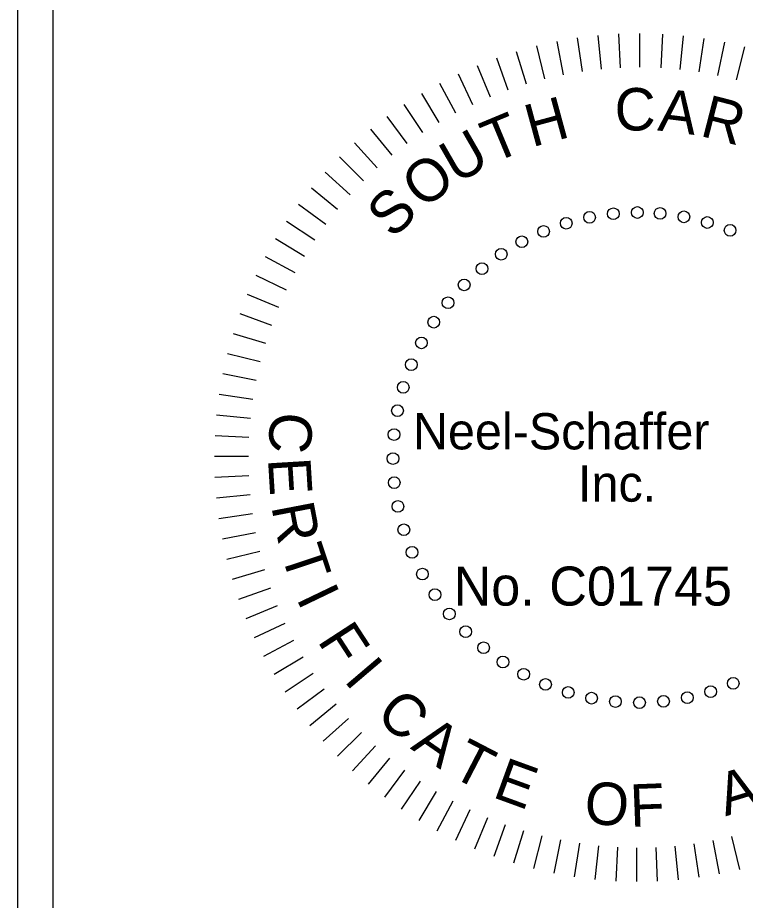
# Model space of a CAD drawing. Extents: x 1524103 to 2096450, y 1024229 to 1162569.
# Drawn here: x 2065607 to 2068303, y 1118769 to 1122041 of the extents above; entities that cross this region are included whole.
import ezdxf

# ---------------------------------------------------------------- set-up
doc = ezdxf.new("R2010")
doc.units = 0
doc.layers.add('RD_SHT_Bndy', color=7, linetype='Continuous')
doc.layers.add('RD_SHT_TX', color=7, linetype='Continuous')

msp = doc.modelspace()

# ---------------------------------------------------------------- linework, layer by layer
at = {"layer": 'RD_SHT_Bndy'}
for points in [[(2065606.8, 1117100.8), (2074607.6, 1117100.8), (2074607.6, 1124635.2), (2065606.8, 1124635.2)], [(2065737.6, 1117227.6), (2074476.9, 1117227.6), (2074476.9, 1124504.5), (2065737.6, 1124504.5)]]:
    msp.add_lwpolyline(points, close=True, dxfattribs=at)
at = {"layer": 'RD_SHT_TX'}
for p, q in [((2067680.3, 1121965.5), (2067698.7, 1121841.4)), ((2067680.3, 1121965.5), (2067698.7, 1121841.4)), ((2067680.3, 1121965.5), (2067698.7, 1121841.4)), ((2067756.9, 1121974.8), (2067769.1, 1121850)), ((2067756.9, 1121974.8), (2067769.1, 1121850)), ((2067756.9, 1121974.8), (2067769.1, 1121850)), ((2067833.7, 1121980.3), (2067839.9, 1121855)), ((2067833.7, 1121980.3), (2067839.9, 1121855)), ((2067833.7, 1121980.3), (2067839.9, 1121855)), ((2067910.8, 1121982.1), (2067910.8, 1121856.7)), ((2067910.8, 1121982.1), (2067910.8, 1121856.7)), ((2067910.8, 1121982.1), (2067910.8, 1121856.7)), ((2067996.6, 1121979.6), (2067989.8, 1121854.4)), ((2067996.6, 1121979.6), (2067989.8, 1121854.4)), ((2067996.6, 1121979.6), (2067989.8, 1121854.4)), ((2068073.5, 1121973.4), (2068060.5, 1121848.6)), ((2068073.5, 1121973.4), (2068060.5, 1121848.6)), ((2068073.5, 1121973.4), (2068060.5, 1121848.6)), ((2068149.9, 1121963.4), (2068130.8, 1121839.4)), ((2068149.9, 1121963.4), (2068130.8, 1121839.4)), ((2068149.9, 1121963.4), (2068130.8, 1121839.4)), ((2067529.1, 1121935.7), (2067559.6, 1121814)), ((2067529.1, 1121935.7), (2067559.6, 1121814)), ((2067529.1, 1121935.7), (2067559.6, 1121814)), ((2067604.4, 1121952.4), (2067628.8, 1121829.4)), ((2067604.4, 1121952.4), (2067628.8, 1121829.4)), ((2067604.4, 1121952.4), (2067628.8, 1121829.4)), ((2068225.8, 1121949.7), (2068200.6, 1121826.8)), ((2068225.8, 1121949.7), (2068200.6, 1121826.8)), ((2068225.8, 1121949.7), (2068200.6, 1121826.8)), ((2068300.8, 1121932.3), (2068269.7, 1121810.8)), ((2068300.8, 1121932.3), (2068269.7, 1121810.8)), ((2068300.8, 1121932.3), (2068269.7, 1121810.8)), ((2067454.8, 1121915.3), (2067491.2, 1121795.2)), ((2067454.8, 1121915.3), (2067491.2, 1121795.2)), ((2067454.8, 1121915.3), (2067491.2, 1121795.2)), ((2067309.6, 1121863.6), (2067357.5, 1121747.7)), ((2067309.6, 1121863.6), (2067357.5, 1121747.7)), ((2067309.6, 1121863.6), (2067357.5, 1121747.7)), ((2067381.5, 1121891.2), (2067423.8, 1121773.1)), ((2067381.5, 1121891.2), (2067423.8, 1121773.1)), ((2067381.5, 1121891.2), (2067423.8, 1121773.1)), ((2067239, 1121832.5), (2067292.6, 1121719.1)), ((2067239, 1121832.5), (2067292.6, 1121719.1)), ((2067239, 1121832.5), (2067292.6, 1121719.1)), ((2067170.1, 1121798), (2067229.2, 1121687.4)), ((2067170.1, 1121798), (2067229.2, 1121687.4)), ((2067170.1, 1121798), (2067229.2, 1121687.4)), ((2067103, 1121760.1), (2067167.4, 1121652.5)), ((2067103, 1121760.1), (2067167.4, 1121652.5)), ((2067103, 1121760.1), (2067167.4, 1121652.5)), ((2067037.7, 1121719), (2067107.4, 1121614.7)), ((2067037.7, 1121719), (2067107.4, 1121614.7)), ((2067037.7, 1121719), (2067107.4, 1121614.7)), ((2066974.6, 1121674.8), (2067049.3, 1121574)), ((2066974.6, 1121674.8), (2067049.3, 1121574)), ((2066974.6, 1121674.8), (2067049.3, 1121574)), ((2066913.8, 1121627.5), (2066993.3, 1121530.5)), ((2066913.8, 1121627.5), (2066993.3, 1121530.5)), ((2066913.8, 1121627.5), (2066993.3, 1121530.5)), ((2066855.3, 1121577.3), (2066939.4, 1121484.3)), ((2066855.3, 1121577.3), (2066939.4, 1121484.3)), ((2066855.3, 1121577.3), (2066939.4, 1121484.3)), ((2066799.3, 1121524.3), (2066887.9, 1121435.5)), ((2066799.3, 1121524.3), (2066887.9, 1121435.5)), ((2066799.3, 1121524.3), (2066887.9, 1121435.5)), ((2066746, 1121468.6), (2066838.9, 1121384.3)), ((2066746, 1121468.6), (2066838.9, 1121384.3)), ((2066746, 1121468.6), (2066838.9, 1121384.3)), ((2066695.5, 1121410.3), (2066792.4, 1121330.7)), ((2066695.5, 1121410.3), (2066792.4, 1121330.7)), ((2066695.5, 1121410.3), (2066792.4, 1121330.7)), ((2066648, 1121349.7), (2066748.6, 1121274.9)), ((2066648, 1121349.7), (2066748.6, 1121274.9)), ((2066648, 1121349.7), (2066748.6, 1121274.9)), ((2066603.4, 1121286.8), (2066707.6, 1121217)), ((2066603.4, 1121286.8), (2066707.6, 1121217)), ((2066603.4, 1121286.8), (2066707.6, 1121217)), ((2066562, 1121221.7), (2066669.5, 1121157.2)), ((2066562, 1121221.7), (2066669.5, 1121157.2)), ((2066562, 1121221.7), (2066669.5, 1121157.2)), ((2066523.9, 1121154.8), (2066634.4, 1121095.5)), ((2066523.9, 1121154.8), (2066634.4, 1121095.5)), ((2066523.9, 1121154.8), (2066634.4, 1121095.5)), ((2066489, 1121086), (2066602.3, 1121032.3)), ((2066489, 1121086), (2066602.3, 1121032.3)), ((2066489, 1121086), (2066602.3, 1121032.3)), ((2066457.6, 1121015.6), (2066573.4, 1120967.5)), ((2066457.6, 1121015.6), (2066573.4, 1120967.5)), ((2066457.6, 1121015.6), (2066573.4, 1120967.5)), ((2066429.7, 1120943.8), (2066547.7, 1120901.4)), ((2066429.7, 1120943.8), (2066547.7, 1120901.4)), ((2066429.7, 1120943.8), (2066547.7, 1120901.4)), ((2066405.3, 1120870.6), (2066525.2, 1120834.1)), ((2066405.3, 1120870.6), (2066525.2, 1120834.1)), ((2066405.3, 1120870.6), (2066525.2, 1120834.1)), ((2066384.5, 1120796.4), (2066506.1, 1120765.8)), ((2066384.5, 1120796.4), (2066506.1, 1120765.8)), ((2066384.5, 1120796.4), (2066506.1, 1120765.8)), ((2066367.4, 1120721.2), (2066490.4, 1120696.6)), ((2066367.4, 1120721.2), (2066490.4, 1120696.6)), ((2066367.4, 1120721.2), (2066490.4, 1120696.6)), ((2066354, 1120645.3), (2066478, 1120626.8)), ((2066354, 1120645.3), (2066478, 1120626.8)), ((2066354, 1120645.3), (2066478, 1120626.8)), ((2066344.3, 1120568.8), (2066469.1, 1120556.4)), ((2066344.3, 1120568.8), (2066469.1, 1120556.4)), ((2066344.3, 1120568.8), (2066469.1, 1120556.4)), ((2066338.4, 1120492), (2066463.7, 1120485.7)), ((2066338.4, 1120492), (2066463.7, 1120485.7)), ((2066338.4, 1120492), (2066463.7, 1120485.7)), ((2066336.3, 1120414.9), (2066461.7, 1120414.8)), ((2066336.3, 1120414.9), (2066461.7, 1120414.8)), ((2066336.3, 1120414.9), (2066461.7, 1120414.8)), ((2066338, 1120337.9), (2066463.2, 1120343.8)), ((2066338, 1120337.9), (2066463.2, 1120343.8)), ((2066338, 1120337.9), (2066463.2, 1120343.8)), ((2066343.4, 1120261), (2066468.2, 1120273.1)), ((2066343.4, 1120261), (2066468.2, 1120273.1)), ((2066343.4, 1120261), (2066468.2, 1120273.1)), ((2066352.6, 1120184.4), (2066476.7, 1120202.7)), ((2066352.6, 1120184.4), (2066476.7, 1120202.7)), ((2066352.6, 1120184.4), (2066476.7, 1120202.7)), ((2066365.5, 1120108.4), (2066488.6, 1120132.7)), ((2066365.5, 1120108.4), (2066488.6, 1120132.7)), ((2066365.5, 1120108.4), (2066488.6, 1120132.7)), ((2066382.2, 1120033.2), (2066503.9, 1120063.5)), ((2066382.2, 1120033.2), (2066503.9, 1120063.5)), ((2066382.2, 1120033.2), (2066503.9, 1120063.5)), ((2066402.5, 1119958.8), (2066522.6, 1119995)), ((2066402.5, 1119958.8), (2066522.6, 1119995)), ((2066402.5, 1119958.8), (2066522.6, 1119995)), ((2066426.4, 1119885.5), (2066544.6, 1119927.6)), ((2066426.4, 1119885.5), (2066544.6, 1119927.6)), ((2066426.4, 1119885.5), (2066544.6, 1119927.6)), ((2066453.9, 1119813.5), (2066569.9, 1119861.3)), ((2066453.9, 1119813.5), (2066569.9, 1119861.3)), ((2066453.9, 1119813.5), (2066569.9, 1119861.3)), ((2066484.9, 1119743), (2066598.4, 1119796.4)), ((2066484.9, 1119743), (2066598.4, 1119796.4)), ((2066484.9, 1119743), (2066598.4, 1119796.4)), ((2066519.4, 1119674), (2066630.1, 1119732.9)), ((2066519.4, 1119674), (2066630.1, 1119732.9)), ((2066519.4, 1119674), (2066630.1, 1119732.9)), ((2066557.1, 1119606.8), (2066664.8, 1119671.1)), ((2066557.1, 1119606.8), (2066664.8, 1119671.1)), ((2066557.1, 1119606.8), (2066664.8, 1119671.1)), ((2066598.1, 1119541.5), (2066702.5, 1119611)), ((2066598.1, 1119541.5), (2066702.5, 1119611)), ((2066598.1, 1119541.5), (2066702.5, 1119611)), ((2066642.3, 1119478.3), (2066743.2, 1119552.8)), ((2066642.3, 1119478.3), (2066743.2, 1119552.8)), ((2066642.3, 1119478.3), (2066743.2, 1119552.8)), ((2066689.5, 1119417.4), (2066786.6, 1119496.8)), ((2066689.5, 1119417.4), (2066786.6, 1119496.8)), ((2066689.5, 1119417.4), (2066786.6, 1119496.8)), ((2066739.6, 1119358.8), (2066832.7, 1119442.9)), ((2066739.6, 1119358.8), (2066832.7, 1119442.9)), ((2066739.6, 1119358.8), (2066832.7, 1119442.9)), ((2066792.6, 1119302.8), (2066881.4, 1119391.3)), ((2066792.6, 1119302.8), (2066881.4, 1119391.3)), ((2066792.6, 1119302.8), (2066881.4, 1119391.3)), ((2066848.2, 1119249.4), (2066932.6, 1119342.2)), ((2066848.2, 1119249.4), (2066932.6, 1119342.2)), ((2066848.2, 1119249.4), (2066932.6, 1119342.2)), ((2066906.4, 1119198.9), (2066986.2, 1119295.6)), ((2066906.4, 1119198.9), (2066986.2, 1119295.6)), ((2066906.4, 1119198.9), (2066986.2, 1119295.6)), ((2066967, 1119151.2), (2067041.9, 1119251.8)), ((2066967, 1119151.2), (2067041.9, 1119251.8)), ((2066967, 1119151.2), (2067041.9, 1119251.8)), ((2067029.8, 1119106.6), (2067099.7, 1119210.7)), ((2067029.8, 1119106.6), (2067099.7, 1119210.7)), ((2067029.8, 1119106.6), (2067099.7, 1119210.7)), ((2067094.8, 1119065.1), (2067159.5, 1119172.5)), ((2067094.8, 1119065.1), (2067159.5, 1119172.5)), ((2067094.8, 1119065.1), (2067159.5, 1119172.5)), ((2067161.7, 1119026.8), (2067221.1, 1119137.3)), ((2067161.7, 1119026.8), (2067221.1, 1119137.3)), ((2067161.7, 1119026.8), (2067221.1, 1119137.3)), ((2067230.4, 1118991.9), (2067284.3, 1119105.1)), ((2067230.4, 1118991.9), (2067284.3, 1119105.1)), ((2067230.4, 1118991.9), (2067284.3, 1119105.1)), ((2067300.8, 1118960.4), (2067349, 1119076.1)), ((2067300.8, 1118960.4), (2067349, 1119076.1)), ((2067300.8, 1118960.4), (2067349, 1119076.1)), ((2067372.6, 1118932.3), (2067415.1, 1119050.3)), ((2067372.6, 1118932.3), (2067415.1, 1119050.3)), ((2067372.6, 1118932.3), (2067415.1, 1119050.3)), ((2067445.7, 1118907.8), (2067482.4, 1119027.8)), ((2067445.7, 1118907.8), (2067482.4, 1119027.8)), ((2067445.7, 1118907.8), (2067482.4, 1119027.8)), ((2067519.9, 1118887), (2067550.6, 1119008.6)), ((2067519.9, 1118887), (2067550.6, 1119008.6)), ((2067519.9, 1118887), (2067550.6, 1119008.6)), ((2067595, 1118869.8), (2067619.8, 1118992.7)), ((2067595, 1118869.8), (2067619.8, 1118992.7)), ((2067595, 1118869.8), (2067619.8, 1118992.7)), ((2068207.8, 1118867.1), (2068183.7, 1118990.1)), ((2068207.8, 1118867.1), (2068183.7, 1118990.1)), ((2068207.8, 1118867.1), (2068183.7, 1118990.1)), ((2068283.1, 1118883.6), (2068253, 1119005.3)), ((2068283.1, 1118883.6), (2068253, 1119005.3)), ((2068283.1, 1118883.6), (2068253, 1119005.3)), ((2067670.9, 1118856.3), (2067689.6, 1118980.3)), ((2067670.9, 1118856.3), (2067689.6, 1118980.3)), ((2067670.9, 1118856.3), (2067689.6, 1118980.3)), ((2067747.4, 1118846.5), (2067760, 1118971.3)), ((2067747.4, 1118846.5), (2067760, 1118971.3)), ((2067747.4, 1118846.5), (2067760, 1118971.3)), ((2067824.2, 1118840.5), (2067830.7, 1118965.7)), ((2067824.2, 1118840.5), (2067830.7, 1118965.7)), ((2067824.2, 1118840.5), (2067830.7, 1118965.7)), ((2067901.3, 1118838.3), (2067901.6, 1118963.7)), ((2067901.3, 1118838.3), (2067901.6, 1118963.7)), ((2067901.3, 1118838.3), (2067901.6, 1118963.7)), ((2067978.3, 1118839.8), (2067972.5, 1118965.1)), ((2067978.3, 1118839.8), (2067972.5, 1118965.1)), ((2067978.3, 1118839.8), (2067972.5, 1118965.1)), ((2068055.2, 1118845.1), (2068043.3, 1118970)), ((2068055.2, 1118845.1), (2068043.3, 1118970)), ((2068055.2, 1118845.1), (2068043.3, 1118970)), ((2068131.8, 1118854.2), (2068113.7, 1118978.3)), ((2068131.8, 1118854.2), (2068113.7, 1118978.3)), ((2068131.8, 1118854.2), (2068113.7, 1118978.3))]:
    msp.add_line(p, q, dxfattribs=at)
for centre in [(2067903.4, 1121318.5), (2067903.4, 1121318.5), (2067903.4, 1121318.5), (2067726.1, 1121300.5), (2067726.1, 1121300.5), (2067726.1, 1121300.5), (2067814.3, 1121313.9), (2067814.3, 1121313.9), (2067814.3, 1121313.9), (2067987.5, 1121314.9), (2067987.5, 1121314.9), (2067987.5, 1121314.9), (2068075.9, 1121302.5), (2068075.9, 1121302.5), (2068075.9, 1121302.5), (2067639.7, 1121278.6), (2067639.7, 1121278.6), (2067639.7, 1121278.6), (2068162.6, 1121281.5), (2068162.6, 1121281.5), (2068162.6, 1121281.5), (2068246.9, 1121252.2), (2068246.9, 1121252.2), (2068246.9, 1121252.2), (2067555.7, 1121248.3), (2067555.7, 1121248.3), (2067555.7, 1121248.3), (2067475.2, 1121209.9), (2067475.2, 1121209.9), (2067475.2, 1121209.9), (2067398.8, 1121163.7), (2067398.8, 1121163.7), (2067398.8, 1121163.7), (2067327.4, 1121110.3), (2067327.4, 1121110.3), (2067327.4, 1121110.3), (2067261.5, 1121050.2), (2067261.5, 1121050.2), (2067261.5, 1121050.2), (2067201.8, 1120983.9), (2067201.8, 1120983.9), (2067201.8, 1120983.9), (2067148.9, 1120912), (2067148.9, 1120912), (2067148.9, 1120912), (2067103.3, 1120835.3), (2067103.3, 1120835.3), (2067103.3, 1120835.3), (2067065.5, 1120754.5), (2067065.5, 1120754.5), (2067065.5, 1120754.5), (2067035.8, 1120670.4), (2067035.8, 1120670.4), (2067035.8, 1120670.4), (2067014.4, 1120583.8), (2067014.4, 1120583.8), (2067014.4, 1120583.8), (2067001.7, 1120495.4), (2067001.7, 1120495.4), (2067001.7, 1120495.4), (2066997.7, 1120406.3), (2066997.7, 1120406.3), (2066997.7, 1120406.3), (2067002.4, 1120317.2), (2067002.4, 1120317.2), (2067002.4, 1120317.2), (2067015.9, 1120229), (2067015.9, 1120229), (2067015.9, 1120229), (2067038, 1120142.6), (2067038, 1120142.6), (2067038, 1120142.6), (2067068.4, 1120058.7), (2067068.4, 1120058.7), (2067068.4, 1120058.7), (2067106.9, 1119978.2), (2067106.9, 1119978.2), (2067106.9, 1119978.2), (2067153.2, 1119901.9), (2067153.2, 1119901.9), (2067153.2, 1119901.9), (2067206.7, 1119830.5), (2067206.7, 1119830.5), (2067206.7, 1119830.5), (2067266.9, 1119764.7), (2067266.9, 1119764.7), (2067266.9, 1119764.7), (2067333.3, 1119705.1), (2067333.3, 1119705.1), (2067333.3, 1119705.1), (2067405.2, 1119652.3), (2067405.2, 1119652.3), (2067405.2, 1119652.3), (2067482, 1119606.9), (2067482, 1119606.9), (2067482, 1119606.9), (2067562.9, 1119569.1), (2067562.9, 1119569.1), (2067562.9, 1119569.1), (2068258.7, 1119573.1), (2068258.7, 1119573.1), (2068258.7, 1119573.1), (2067647, 1119539.5), (2067647, 1119539.5), (2067647, 1119539.5), (2067733.7, 1119518.3), (2067733.7, 1119518.3), (2067733.7, 1119518.3), (2068088.4, 1119520.3), (2068088.4, 1119520.3), (2068088.4, 1119520.3), (2068174.8, 1119542.5), (2068174.8, 1119542.5), (2068174.8, 1119542.5), (2067822, 1119505.7), (2067822, 1119505.7), (2067822, 1119505.7), (2067911.2, 1119501.8), (2067911.2, 1119501.8), (2067911.2, 1119501.8), (2068000.2, 1119506.7), (2068000.2, 1119506.7), (2068000.2, 1119506.7)]:
    msp.add_circle(centre, 21.7, dxfattribs=at)

# ---------------------------------------------------------------- texts
for s, rotation, p in [('C', 0.349, (2067819.5, 1121622)), ('A', 352.9661, (2067975.8, 1121623)), ('H', 15.1734, (2067512.6, 1121559.9)), ('R', 345.5832, (2068130.9, 1121603.8)), ('T', 22.5564, (2067368.3, 1121499.9)), ('U', 29.9393, (2067232.8, 1121422)), ('O', 37.3222, (2067108.6, 1121327.2)), ('S', 44.7051, (2066997.5, 1121217.3)), ('C', 266.1111, (2066544.9, 1120582.1)), ('E', 273.494, (2066534.3, 1120405.9)), ('R', 280.8769, (2066546.4, 1120229.8)), ('T', 288.2598, (2066581, 1120056.8)), ('I', 295.6427, (2066637.5, 1119889.6)), ('F', 303.0257, (2066715.1, 1119731)), ('I', 310.4086, (2066812.4, 1119583.8)), ('C', 317.7915, (2066927.8, 1119450.3)), ('A', 325.1744, (2067059.4, 1119332.7)), ('T', 332.5573, (2067205, 1119233)), ('E', 339.9402, (2067362.2, 1119152.8)), ('A', 16.972, (2068229.7, 1119079.8)), ('O', 354.7647, (2067702.3, 1119055.8)), ('F', 2.1476, (2067878.2, 1119041.1))]:
    msp.add_text(s, height=157.3, rotation=rotation, dxfattribs=at).set_placement(p)
for s, height, p in [('Neel-Schaffer ', 134.442, (2067071.6, 1120440.4)), ('Neel-Schaffer ', 134.442, (2067071.6, 1120440.4)), ('Neel-Schaffer ', 134.442, (2067071.6, 1120440.4)), ('Inc.', 134.44, (2067683.4, 1120246.6)), ('Inc.', 134.44, (2067683.4, 1120246.6)), ('Inc.', 134.44, (2067683.4, 1120246.6)), ('No. C01745', 144.6, (2067222.2, 1119861.4)), ('No. C01745', 144.6, (2067222.2, 1119861.4)), ('No. C01745', 144.6, (2067222.2, 1119861.4))]:
    msp.add_text(s, height=height, dxfattribs=at).set_placement(p)

doc.saveas('drawing.dxf')
